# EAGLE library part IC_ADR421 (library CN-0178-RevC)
Ultraprecision, Low Noise, 2.500 V XFET® Voltage References
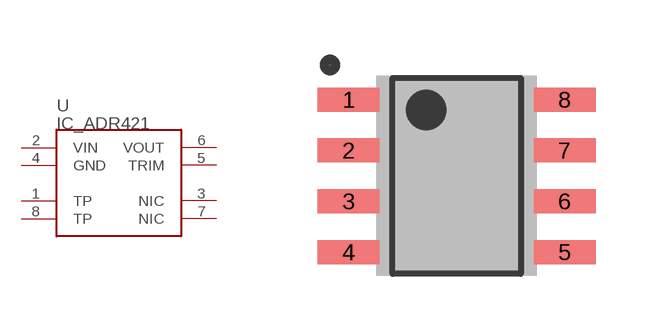
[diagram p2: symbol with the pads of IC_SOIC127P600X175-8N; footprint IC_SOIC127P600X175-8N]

Designator prefix U

## IC_ADR421_SOIC8  [IC_SOIC127P600X175-8N]
1  TP  pas
2  VIN  pas
3  NIC  pas
4  GND  pas
5  TRIM  pas
6  VOUT  pas
7  NIC  pas
8  TP  pas

## Footprint IC_SOIC127P600X175-8N (pad centres in mm)
(SOIC-8) 1.27mm pitch; 3.90mm W X 4.90mm L X 1.75mm H body; JEDEC MS-012AA
smd 1.55 x 0.6: 1 -2.7,1.905; 2 -2.7,0.635; 3 -2.7,-0.635; 4 -2.7,-1.905; 5 2.7,-1.905; 6 2.7,-0.635; 7 2.7,0.635; 8 2.7,1.905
